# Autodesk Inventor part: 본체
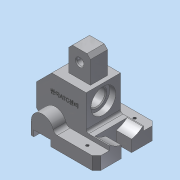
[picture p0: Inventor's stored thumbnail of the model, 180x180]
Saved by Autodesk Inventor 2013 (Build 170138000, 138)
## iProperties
Created: 2016-11
Part Number: 본체
Material: 알루미늄 6061
Document SubType Name: Modeling
Designer: Administrator
Density: 2.71 g/cm^3
Mass: 453.586 g
Surface Area: 313.387 cm^2
Volume: 167.375 cm^3
Author: Administrator
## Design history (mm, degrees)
sketch "스케치1"
  geometry: L1 (-38, 35)-(38, 35); L2 (38, 35)-(38, -35); L3 (38, -35)-(-38, -35); L4 (-38, -35)-(-38, 35); 3 further points
  constraints: 8 end point, 2 midpoint, 2 parallel, 1 horizontal, 1 horizontal alignment, 1 perpendicular, 1 vertical alignment
  dimensions: "d0" = 76 distance of L1.start L1.end; "d2" = 70 distance of L1.end L2.end
extrude "돌출1" new body sketch "스케치1" distance "d3" = 15; taper "d4" = 0 deg
sketch "스케치2"
  geometry: L1 (-35, 35)-(-35, -35); L2 (-15, 35)-(-15, -35); L3 (38, 35)-(-38, 35) reference; L4 (-38, -35)-(38, -35) reference; 1 further point
  constraints: 4 end point, 4 point on line, 1 parallel, 1 vertical
  dimensions: "d5" = 20 distance between parallel lines of L2 L1; "d6" = 3 distance from line of L1 L4.start
extrude "돌출2" cut sketch "스케치2" distance "d7" = 7; taper "d8" = 0 deg
sketch "스케치3"
  geometry: L1 (0, 0)-(76, 0) reference; A1 r 13 centre (13, 0) between (26, 0) and (0, 0); 1 further point
  constraints: 2 point on circle, 2 point on line, 1 centre point, 1 end point
  dimensions: "d9" = 26 diameter of A1
extrude "돌출3" join sketch "스케치3" distance "d11" = 70; taper "d12" = 0 deg
node "작업 평면1"
sketch "스케치4"
  geometry: L1 (-47, 20)-(11, 20); L2 (11, 20)-(11, -20); L3 (11, -20)-(-47, -20); L4 (-47, -20)-(-47, 20); L5 (38, -35)-(38, 35) reference; L6 (-38, 35)-(-38, -35) reference; 2 further points
  constraints: 8 end point, 2 parallel, 1 horizontal, 1 horizontal alignment, 1 midpoint, 1 perpendicular
  dimensions: "d115" = 9 distance between parallel lines of L6 L4; "d116" = 58 distance between parallel lines of L2 L4; "d117" = 40 distance between parallel lines of L3 L1
extrude "돌출4" join sketch "스케치4" distance "d18" = 48; taper "d19" = 0 deg
chamfer "모따기1" distance "d20" = 18; stored, may be unused: second distance "d21" = 2, angle "d22" = 45 deg
chamfer "모따기2" distance "d23" = 4; stored, may be unused: second distance "d24" = 2, angle "d25" = 45 deg
chamfer "모따기3" distance "d26" = 5; stored, may be unused: second distance "d27" = 2, angle "d28" = 45 deg
chamfer "모따기4" distance "d29" = 5; stored, may be unused: second distance "d30" = 2, angle "d31" = 45 deg
fillet "모깎기1" dims "d32" = 5
node "작업 평면2"
sketch "스케치5"
  geometry: L1 (-19, 10)-(6, 10); L2 (6, 10)-(6, -10); L3 (6, -10)-(-19, -10); L4 (-19, -10)-(-19, 10); L5 (11, 20)-(11, -20) reference; 2 further points
  constraints: 8 end point, 2 parallel, 1 horizontal, 1 horizontal alignment, 1 midpoint, 1 perpendicular
  dimensions: "d34" = 5 distance between parallel lines of L2 L5; "d35" = 25 distance of L1.start L1.end; "d36" = 20 distance of L1.end L2.end
extrude "돌출5" join sketch "스케치5" distance "d37" = 40; taper "d38" = 0 deg
chamfer "모따기5" distance "d39" = 4; stored, may be unused: second distance "d40" = 2, angle "d41" = 45 deg
node "작업 평면3"
node "작업 평면5"
  node "작업 평면4"
sketch "스케치8"
  geometry: L1 (11, 20)-(11, -20) reference; L2 (11, 20)-(38, 20); L3 (38, 20)-(38, -20); L4 (38, -20)-(11, -20); L5 (11, -20)-(11, 20); L6 (-29, 20)-(11, 20) reference; L7 (11, -20)-(-29, -20) reference; 4 further points; 1 other entity
  constraints: 8 end point, 2 collinear, 2 parallel, 1 horizontal, 1 perpendicular, 1 point on line, 1 vertical, 1 other
extrude "돌출7" join sketch "스케치8" distance "d49" = 5; taper "d50" = 0 deg
sketch "스케치9"
  geometry: L1 (-5, 36)-(15, 36); L2 (15, 36)-(15, 24); L3 (15, 24)-(-5, 24); L4 (-5, 24)-(-5, 36); L5 (15, 60)-(15, 0) reference; L6 (0, 60)-(15, 60) reference; L7 (0, 50)-(0, 60) reference; L8 (0, 50)-(-5, 50) reference; L9 (-5, 10)-(-5, 50) reference; L10 (0, 10)-(-5, 10) reference; L11 (0, 0)-(0, 10) reference; L12 (15, 0)-(0, 0) reference; L13 (15, 60)-(15, 0) reference; 4 further points
  constraints: 8 end point, 5 midpoint, 2 parallel, 1 horizontal, 1 horizontal alignment, 1 perpendicular
  dimensions: "d51" = 12 distance of L1.end L2.end
extrude "돌출8" cut sketch "스케치9" distance "d53" = 18; taper "d54" = 0 deg
node "작업 평면6"
node "작업 평면7"
node "작업 평면8"
node "작업 평면9"
sketch "스케치14"
  geometry: L1 (-5, -38.894)-(-5, -1.106); L2 (-5, -14)-(-5, 0) reference; L3 (-5, -26)-(-5, -14) reference; L4 (-5, -40)-(-5, -26) reference; C1 r 10 at (-27, -20) reference; A1 r 29 centre (-27, -20) between (-5, -38.894) and (-5, -1.106); 1 further point
  constraints: 2 end point, 2 point on circle, 2 point on line, 1 centre point, 1 coincident, 1 collinear, 1 vertical
  dimensions: "d68" = 58 diameter of A1
extrude "돌출9" cut sketch "스케치14" distance "d70" = 18; taper "d71" = 0 deg
sketch "스케치15"
  geometry: L1 (-46, -20)-(-46, 20) reference; L2 (-46, 20)-(-38, 20) reference; L3 (-38, 20)-(-38, 35) reference; L4 (-38, 35)-(-7.708, 35) reference; L5 (-7.708, 20)-(-7.708, 35) reference; L6 (-7.708, 20)-(38, 20) reference; L7 (38, 20)-(38, 10.583) reference; L8 (38, 10.583)-(20, 10.583) reference; L9 (20, 10.583)-(20, -10.583) reference; L10 (20, -10.583)-(38, -10.583) reference; L11 (38, -10.583)-(38, -20) reference; L12 (38, -20)-(38, -30) reference; L13 (38, -30)-(33, -35) reference; L14 (33, -35)-(-7.708, -35) reference; L15 (-7.708, -35)-(-38, -35) reference; L16 (-38, -35)-(-38, -20) reference; L17 (-38, -20)-(-46, -20) reference; L18 (-7.708, 35)-(33, 35) reference; L19 (33, 35)-(38, 30) reference; L20 (38, 30)-(38, 20) reference; L21 (38, -20)-(-7.708, -20) reference; L22 (-7.708, -35)-(-7.708, -20) reference; L23 (11, 20)-(11, -20) reference; 3 further points
  constraints: 1 vertical alignment
  dimensions: "d72" = 55 distance of point (20, -27.5) point (20, 27.5); "d74" = 27.5 vertical distance of point (0, 0) point (20, 27.5); "d76" = 18 distance from line of point (20, 27.5) L20
hole "구멍2" sketch "스케치15" at (20, 27.5), (20, -27.5) diameter "d77" = 3.242; stored, may be unused: countersink angle "d81" = 90 deg, drill point angle "d83" = 0 deg; dims "d78" = 28, "d79" = 29, "d80" = 7, "d82" = 30
fillet "모깎기2" dims "d84" = 3
sketch "스케치16"
  geometry: L1 (0, 26)-(0, 0) reference; L2 (-16, -53)-(-16, -60) reference; L3 (-16, -60)-(-19, -60) reference; L4 (-19, -60)-(-19, -48) reference; L5 (-19, -48)-(-24, -48) reference; L6 (-24, -48)-(-28, -44) reference; L7 (-28, -44)-(-28, -18) reference; L8 (-28, -18)-(-10, 0) reference; L9 (-10, 0)-(0, 0) reference; L10 (0, 0)-(0, 26) reference; L11 (0, 26)-(4, 30) reference; L12 (4, 30)-(21, 30) reference; L13 (21, 30)-(25, 26) reference; L14 (25, 26)-(25, 0) reference; L15 (25, 0)-(30, 0) reference; L16 (30, 0)-(30, -37) reference; L17 (4, -53)-(-16, -53) reference; L18 (4, -60)-(4, -53) reference; L19 (57, -60)-(4, -60) reference; L20 (57, -45.221)-(57, -60) reference; L21 (39, -45.221)-(57, -45.221) reference; L22 (39, -40)-(39, -45.221) reference; L23 (33, -40)-(39, -40) reference; L24 (0, 0)-(25, 0) reference; L25 (57, -45)-(11.292, -45) reference; L26 (57, -45)-(57, -40) reference; L27 (33, -40)-(57, -40) reference; L28 (30, 0)-(30, -37) reference; L29 (30, 0)-(-10, 0) reference; L30 (-28, -18)-(-10, 0) reference; L31 (-28, -18)-(-28, -44) reference; L32 (-24, -48)-(-28, -44) reference; L33 (-19, -48)-(-24, -48) reference; L34 (-19, -45)-(-19, -48) reference; L35 (22, -32.5)-(22, -3.5) reference; L36 (22, -32.5)-(22, -3.5) reference; L37 (30, -3.5)-(30, -32.5) reference; A1 r 3 centre (33, -37) between (30, -37) and (33, -40) reference; A2 r 5 centre (11.292, -40) between (6.488, -41.389) and (11.292, -45) reference; A3 r 3 centre (33, -37) between (30, -37) and (33, -40) reference; A4 r 13 centre (-6, -45) between (6.488, -41.389) and (-19, -45) reference; 3 further points
  dimensions: "d88" = 12.5 distance from line of point (12.5, 17) L1; "d89" = 35 vertical distance of point (21, -18) point (12.5, 17)
hole "구멍3" sketch "스케치16" at (12.5, 17) diameter "d90" = 8; stored, may be unused: countersink angle "d94" = 90 deg, drill point angle "d96" = 0 deg; dims "d91" = 28, "d92" = 29, "d93" = 7, "d95" = 30
chamfer "모따기7" distance "d97" = 1; stored, may be unused: second distance "d98" = 2, angle "d99" = 45 deg
sketch "스케치17"
  geometry: L1 (49, 48)-(9, 48) reference; L2 (49, 48)-(49, 11) reference; 3 further points
  constraints: 1 coincident, 1 other
  dimensions: "d100" = 18 distance from line of point (24, 30) L1; "d101" = 25 distance from line of point (24, 30) L2
feature "엠보싱1" sketch "스케치17" dims "d0" = 76, "d2" = 70, "d102" = 0.5, "d103" = 0
sketch "스케치18"
  geometry: L1 (60, 50)-(60, 26) reference; L2 (37, 40)-(37, 0) reference; L3 (0, 40)-(37, 40) reference; L4 (0, 40)-(0, 0) reference; L5 (0, 0)-(37, 0) reference; 3 further points
  constraints: 1 horizontal alignment, 1 midpoint
  dimensions: "d104" = 42 distance from line of point (18, 20) L1
hole "구멍4" sketch "스케치18" at (18, 20) diameter "d105" = 20; stored, may be unused: countersink angle "d109" = 90 deg, drill point angle "d111" = 0 deg; dims "d106" = 6, "d107" = 29, "d108" = 7, "d110" = 8
chamfer "모따기8" distance "d112" = 1; stored, may be unused: second distance "d113" = 2, angle "d114" = 45 deg
node "솔리드1"
node "투영된 루프2"
node "투영된 루프3"
node "투영된 루프5"
node "절단 모서리 투영1"
node "절단 모서리 투영2"
other parameters: "d44" = 37, "d57" = -18, "d59" = 5
